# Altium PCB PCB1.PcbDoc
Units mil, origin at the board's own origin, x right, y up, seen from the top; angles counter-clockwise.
Board outline 3898.32 x 3898.32 mil, 2 copper layers (Top Layer, Bottom Layer); 54 components, 45 nets, 223 pads, 46 vias.
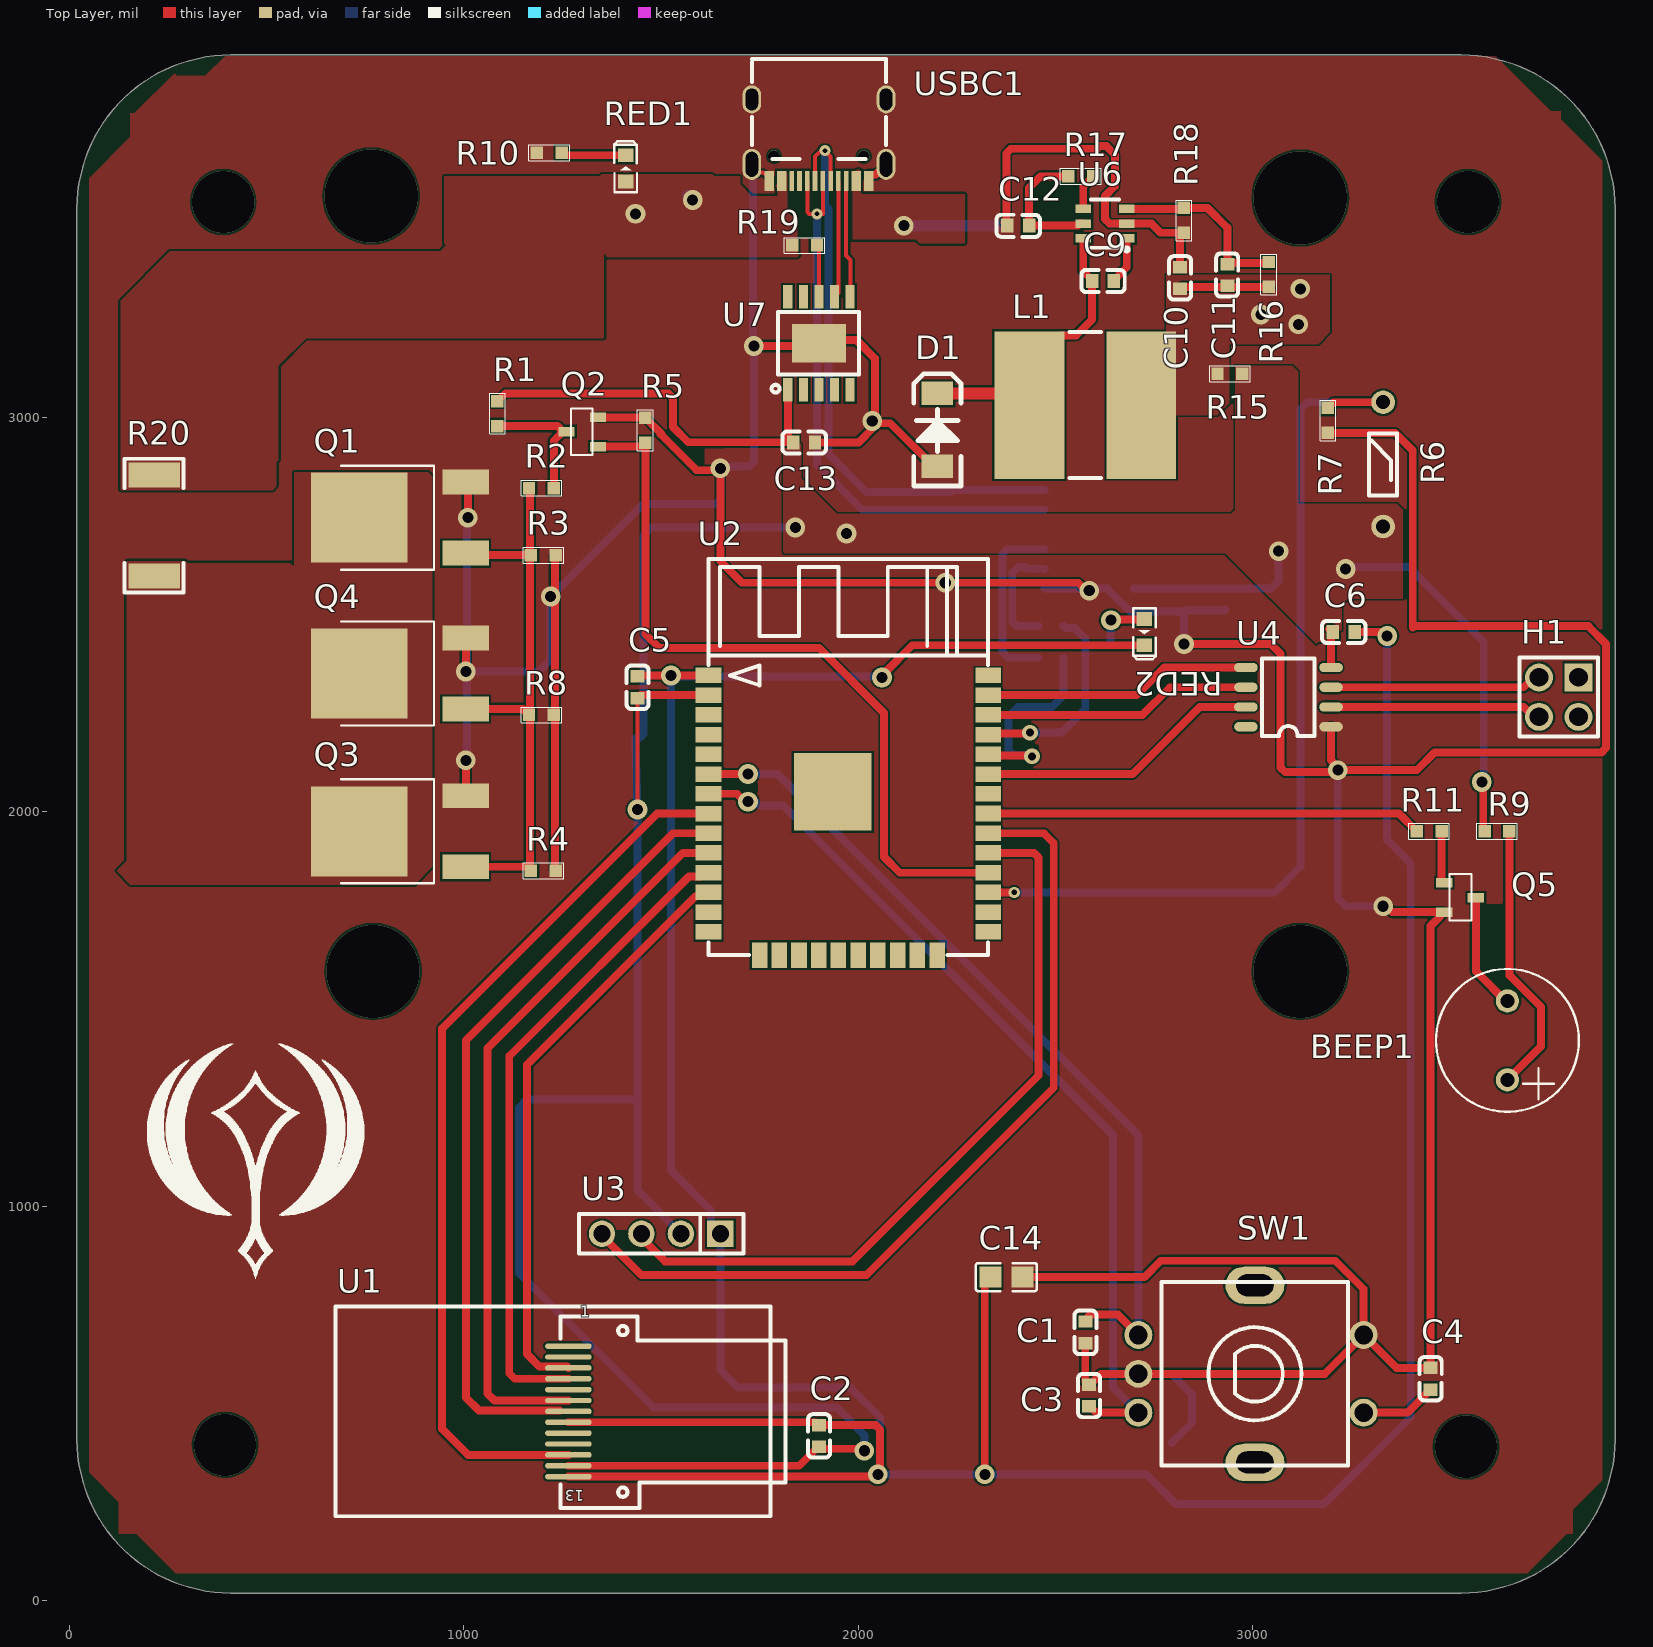
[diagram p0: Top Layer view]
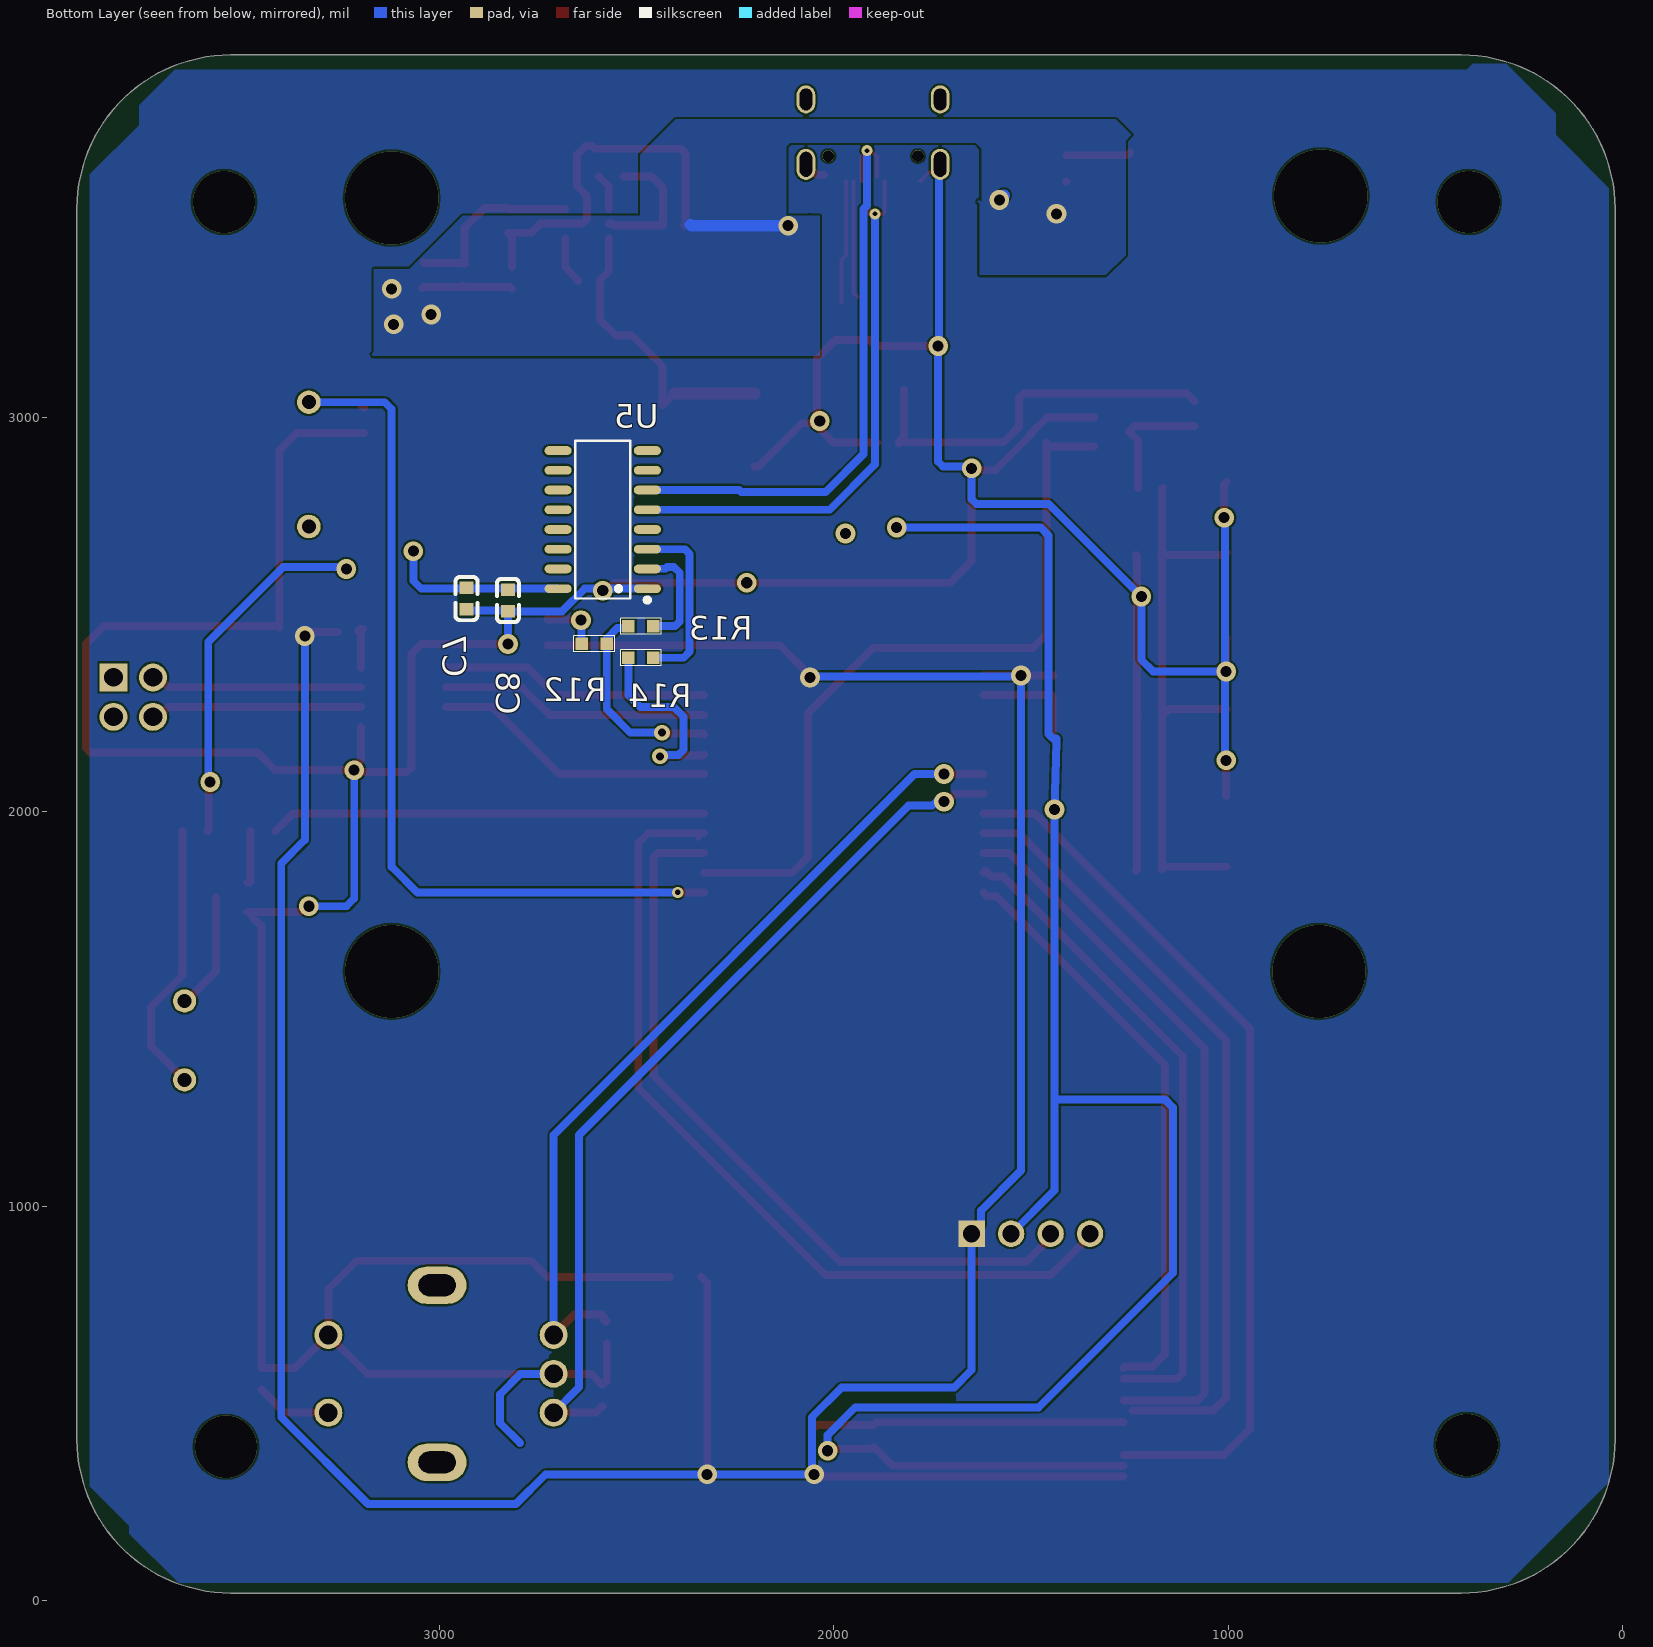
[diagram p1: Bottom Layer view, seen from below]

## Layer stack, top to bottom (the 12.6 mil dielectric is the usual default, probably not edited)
Top Solder: solder mask 0.4, Solder Resist, Dk 3.5
Top Layer: signal copper 1.4
Dielectric 1: dielectric 12.6, FR-4, Dk 4.8
Bottom Layer: signal copper 1.4
Bottom Solder: solder mask 0.4, Solder Resist, Dk 3.5

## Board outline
19.35,409.18 19.35,3527.83 cw(c409.18,3527.83) 409.18,3917.66 3527.83,3917.66 cw(c3527.83,3527.83) 3917.66,3527.83 3917.66,409.18 cw(c3527.83,409.18) 3527.83,19.35 409.18,19.35 cw(c409.18,409.18)

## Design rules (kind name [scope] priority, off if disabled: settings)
Clearance [All] p1: gap=5 ignorepadtopadclearanceinfootprint=TRUE
PolygonConnect [All] p1: connectstyle=Direct reliefconductorwidth=10 reliefentries=4 polygonreliefangle="90 Angle" airgapwidth=10
RoutingVias [All] p1: holewidth=28 width=50 viastyle="Through Hole" minholewidth=28 minwidth=50 maxholewidth=28 maxwidth=50
SolderMaskExpansion [All] p1: expansion=4
Width [All] p1: maxlimit=100 minlimit=10 preferedwidth=20
30 further rules are at their usual default settings.

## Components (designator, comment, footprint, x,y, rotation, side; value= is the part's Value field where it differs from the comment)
BEEP1 "BEEP-9.5X5.5" BEEP-9.5X5.5 3645,1420 r90 top
C1 "100nf" C0603 2575,680 r90 top
C2 "C0603" C0603 1900,417.56 r90 top
C3 "100nf" C0603 2585,520 r270 top
C4 "100nf" C0603 3450,562.56 r90 top
C5 "100NF" C0603 1440,2315 r90 top
C6 "C0603" C0603 3230,2455 r180 top
C7 "10UF" C0603 2930,2540 r270 bottom
C8 "0.1UF" C0603 2825,2535 r270 bottom
C9 "1UF" C0603 2620,3345 r0 top
C10 "100UF" C0603 2815,3352.56 r90 top
C11 "440P~660P" C0603 2935,3360 r270 top
C12 "10UF" C0603 2405,3485 r0 top
C13 "1uF" C0603 1862.44,2935 r180 top
C14 "C0805" C0805 2375,820 r180 top
D1 "SMAJ5.0CA" DO-214 2200,2875 r90 top
H1 "A2541WV-2X2P" HDR-TH_4P-P2.54-V-R2-C2-S2.54_A2541WV-2X2P 3775,2290 r180 top
L1 "6.8uH" IND-SMD_L10.0-W9.0 2575,3030 r0 top
Q1 "NCE3050K" TO-252-2_L6.6-W6.1-P4.57-LS10.1-TL-CW 869.81,2745 r180 top
Q2 "S8050" SOT-23 1340,2925 r90 top
Q3 "NCE3050K" TO-252-2_L6.6-W6.1-P4.57-LS10.1-TL-CW 869.81,1950 r180 top
Q4 "NCE3050K/NC" TO-252-2_L6.6-W6.1-P4.57-LS10.1-TL-CW 869.81,2350 r180 top
Q5 "S8050" SOT-23 3485,1819.8 r270 top
R1 "R0603" R_0603 1085,2977.01 r90 top value=3K
R2 "R0603" R_0603 1227.99,2820 r180 top value=100R
R3 "R0603" R_0603 1232.99,2650 r180 top value=100K
R4 "R0603" R_0603 1232.99,1850 r180 top value=100K
R5 "R0603" R_0603 1460,2997.99 r270 top value=10K
R6 "100kΩ/nc" RES-TH_BD1.8-L4.0-P8.00-D0.5 3330,2880 r90 top
R7 "R0603" R_0603 3190,3022.99 r270 top value=100K/nc
R8 "R0603" R_0603 1227.99,2245 r180 top value=10K/NC
R9 "R0603" R_0603 3650,1950 r180 top value=100R
R10 "R0603" R_0603 1247.99,3670 r180 top value=500R
R11 "R0603" R_0603 3415,1950 r0 top value=10K
R12 "R0603" R_0603 2575,2425 r0 bottom value=500R
R13 "R0603" R_0603 2520,2470 r180 bottom value=10R
R14 "R0603" R_0603 2520,2390 r180 bottom value=10R
R15 "R0603" R_0603 2910,3110 r0 top value=1K
R16 "R0603" R_0603 3040,3392.99 r270 top value=3.3K
R17 "R0603" R_0603 2595,3610 r180 top value=1M
R18 "R0603" R_0603 2825,3467.01 r90 top value=1K
R19 "R0603" R_0603 1895,3435 r180 top value=1K
R20 "加热板" R2512 215,2725 r90 top value=0.01Ω
RED1 "LED-0603_R" LED0603_RED 1410,3630 r90 top
RED2 "LED-0603_R" LED0603_RED 2725,2455 r270 top
SW1 "EC11" SW-TH_5P-L11.8-W12.0-P2.50-LS14.5 2995,575 r270 top
U1 "0.96 TFT" "0.96 LCD" 1265,479.76 r180 top
U2 "ESP32-WROOM-32" WIFIM-SMD_ESP-32S 1974.37,1990.55 r270 top
U3 "OLED" HDR-TH_4P-P2.54-V-M 1500,930 r180 top
U4 "MAX6675" SOIC-8_L5.0-W4.0-P1.27-LS6.0-BL 3090,2290 r90 top
U5 "CH340C" SOP-16_L10.0-W3.9-P1.27-LS6.0-BL 2585,2740 r90 bottom
U6 "ME3116" SOT-23-6_L2.9-W1.6-P0.95-LS2.8-BR 2625,3490 r0 top
U7 "CH224K" ESSOP10-EP 1900,3186.89 r90 top
USBC1 "TYPE-C-31-M-12" USB-C_SMD-TYPE-C-31-M-12 1899.92,3701.68 r180 top

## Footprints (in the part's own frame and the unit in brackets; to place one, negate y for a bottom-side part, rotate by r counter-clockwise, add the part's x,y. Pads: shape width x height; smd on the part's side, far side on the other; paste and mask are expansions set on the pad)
"0.96 LCD" [mm]
  oval 3x0.35 smd: 1(0,-4.2) 2(0,-3.5) 3(0,-2.8) 4(0,-2.1) 5(0,-1.4) 6(0,-0.7) 7(0,0) 8(0,0.7) 9(0,1.4) 10(0,2.1) 11(0,2.8) 12(0,3.5) 13(0,4.2)
  silkscreen extent -13.97,-6.75 15,6.75
BEEP-9.5X5.5 [mm]
  round 1.5 hole 0.9: 1(-2.54,0) 2(2.54,0)
  silkscreen extent -4.6,-4.6 4.6,4.6
C0603 [mm]
  rect 0.8x0.9 smd: 1(0.7,0) 2(-0.7,0)
  silkscreen extent -1.4,-0.72 1.4,0.7
C0805 [mm]
  rect 1.41x1.35 smd: 1(-1.03,0) 2(1.03,0)
  silkscreen extent -1.96,-0.9 1.96,0.9
DO-214 [mil]
  rect 60x80 smd: 1(0,0) 2(185,0)
  silkscreen extent -50,-60 235,60
ESSOP10-EP [mm]
  rect 2.5x3.5 smd: 0(0,0)
  rect 1.5x0.6 smd: 1(-3,2) 2(-3,1) 3(-3,0) 4(-3,-1) 5(-3,-2) 6(3,-2) 7(3,-1) 8(3,0) 9(3,1) 10(3,2)
  silkscreen extent -3.17,-2.57 2,3.05
HDR-TH_4P-P2.54-V-M [mm]
  rect 1.7x1.7 hole 1.1: 1(-3.81,0)
  round 1.7 hole 1.1: 2(-1.27,0) 3(1.27,0) 4(3.81,0)
  silkscreen extent -5.29,-1.27 5.29,1.27
HDR-TH_4P-P2.54-V-R2-C2-S2.54_A2541WV-2X2P [mm]
  rect 1.8x1.8 hole 1.2: 1(-1.27,-1.27)
  round 1.8 hole 1.2: 2(-1.27,1.27) 3(1.27,-1.27) 4(1.27,1.27)
  silkscreen extent -2.54,-2.54 2.54,2.54
IND-SMD_L10.0-W9.0 [mm]
  rect 4.5x9.5 smd: 1(-3.6,0) 2(3.6,0)
  silkscreen extent -1.02,-4.7 1.02,4.7
LED0603_RED [mm]
  rect 0.9x1 smd: 1(-0.85,0) 2(0.85,0)
  silkscreen extent -1.54,-0.73 1.75,0.73
R2512 [mm]
  rect 1.6x3.3 smd: 1(-3.25,0) 2(3.25,0)
  silkscreen extent -4.3,-1.9 4.3,1.9
R_0603 [mm]
  rect 0.8x0.8 smd: 1(0,0) 2(1.6,0)
  silkscreen extent -0.51,-0.51 2.11,0.51
RES-TH_BD1.8-L4.0-P8.00-D0.5 [mil]
  round 60 hole 35.43: 1(-157.48,0) 2(157.48,0)
  silkscreen extent -79,-35 79,35
SOIC-8_L5.0-W4.0-P1.27-LS6.0-BL [mm]
  oval 0.6x1.52 smd: 1(-1.905,-2.74) 2(-0.635,-2.74) 3(0.635,-2.74) 4(1.905,-2.74) 5(1.905,2.74) 6(0.635,2.74) 7(-0.635,2.74) 8(-1.905,2.74)
  silkscreen extent -2.49,-1.67 2.5,1.7
SOP-16_L10.0-W3.9-P1.27-LS6.0-BL [mm]
  oval 0.56x1.745 smd: 1(-4.445,-2.873) 2(-3.175,-2.873) 3(-1.905,-2.873) 4(-0.635,-2.873) 5(0.635,-2.873) 6(1.905,-2.873) 7(3.175,-2.873) 8(4.445,-2.873) 9(4.445,2.873) 10(3.175,2.873) 11(1.905,2.873) 12(0.635,2.873) 13(-0.635,2.873) 14(-1.905,2.873) 15(-3.175,2.873) 16(-4.445,2.873)
  silkscreen extent -5.33,-3.02 5.08,1.77
SOT-23 [mm]
  rect 0.6x1.05 smd: 1(0,0) 2(1.9,0) 3(0.965,2.032)
  silkscreen extent -0.55,0.35 2.45,1.75
SOT-23-6_L2.9-W1.6-P0.95-LS2.8-BR [mm]
  rect 1x0.55 smd: 1(1.4,-0.95) 2(1.4,0) 3(1.4,0.95) 4(-1.4,0.95) 5(-1.4,0) 6(-1.4,-0.95)
  silkscreen extent -0.9,-1.78 1.52,1.55
SW-TH_5P-L11.8-W12.0-P2.50-LS14.5 [mm]
  round 1.8 hole 1.2: 1(-2.5,-7.25) 2(0,-7.25) 3(2.5,-7.25) 4(-2.5,7.25) 5(2.5,7.25)
  oval 2.4x3.8 hole 1.4 slot 2.4 at 90 deg: 7(-5.7,0.25) 8(5.7,0.25)
  silkscreen extent -5.9,-5.75 5.9,6.25
TO-252-2_L6.6-W6.1-P4.57-LS10.1-TL-CW [mm]
  rect 3x1.6 smd: 1(-3.424,2.285) 3(-3.424,-2.285)
  rect 6.2x5.8 smd: 2(3.424,0)
  silkscreen extent -1.38,-3.35 4.58,3.35
USB-C_SMD-TYPE-C-31-M-12 [mm]
  oval 1.2x1.8 hole 0.8 slot 1.4 at 90 deg: 0(-4.32,-2.624) 0(4.32,-2.624)
  oval 1.2x2 hole 0.8 slot 1.6 at 90 deg: 0(-4.32,1.556) 0(4.32,1.556)
  rect 0.3x1.3 smd: A1(-3.35,2.623) A4(-2.55,2.623) A5(-1.25,2.623) A6(-0.25,2.623) A7(0.25,2.623) A8(1.25,2.624) A9(2.55,2.623) A12(3.35,2.623) B1(3.05,2.623) B4(2.25,2.623) B5(1.75,2.623) B6(0.75,2.623) B7(-0.75,2.623) B8(-1.75,2.624) B9(-2.25,2.623) B12(-3.05,2.623)
  round 0.75 hole 0.75 unplated: ""(-2.89,1.026) ""(2.89,1.026)
  silkscreen extent -4.32,-5.23 4.32,1.22
WIFIM-SMD_ESP-32S [mm]
  rect 1x1.65 smd: 1(-9.005,-9) 2(-7.735,-9) 3(-6.465,-9) 4(-5.195,-9) 5(-3.925,-9) 6(-2.655,-9) 7(-1.385,-9) 8(-0.115,-9) 9(1.155,-9) 10(2.425,-9) 11(3.695,-9) 12(4.965,-9) 13(6.235,-9) 14(7.505,-9) 25(7.505,9) 26(6.235,9) 27(4.965,9) 28(3.695,9) 29(2.425,9) 30(1.155,9) 31(-0.115,9) 32(-1.385,9) 33(-2.655,9) 34(-3.925,9) 35(-5.195,9) 36(-6.465,9) 37(-7.735,9) 38(-9.005,9)
  rect 1.65x1 smd: 15(9.005,-5.715) 16(9.005,-4.445) 17(9.005,-3.175) 18(9.005,-1.905) 19(9.005,-0.635) 20(9.005,0.635) 21(9.005,1.905) 22(9.005,3.175) 23(9.005,4.445) 24(9.005,5.715)
  rect 5x5 smd: 39(-1.51,-1)
  silkscreen extent -16.5,-9 9,9

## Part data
C1 C3 C4 C5 C7 C8 C9 C10 C11 C12 C13: library part C0603, BOM_Manufacturer="Samsung Electro-Mechanics", BOM_Manufacturer Part=10uF
C2 C6: BOM_Manufacturer="Samsung Electro-Mechanics", BOM_Manufacturer Part=10uF
C14: "Capacitor"
D1: "500V  400W 稳压管"
H1: library part 2X2P, BOM_JLCPCB Part Class="Extended Part", BOM_Manufacturer="Changjiang Connectors", BOM_Manufacturer Part=A2541WV-2x2P
L1: BOM_Manufacturer=LCSC, BOM_Manufacturer Part=SM1054-6R8MT
Q1 Q3: BOM_JLCPCB Part Class="Extended Part", BOM_Manufacturer=Ncepower
Q2 Q5: "NPN", Manufacturer #2=8050
Q4: library part NCE3050K, BOM_JLCPCB Part Class="Extended Part", BOM_Manufacturer=Ncepower
R6: library part "NTC 100kΩ", BOM_JLCPCB Part Class="Extended Part", BOM_Manufacturer=Shiheng, BOM_Manufacturer Part=MF58-104J3950F
R20: library part R2501, "R2501", BOM_JLCPCB SMD=Yes, BOM_Manufacturer=SUP, BOM_Manufacturer Part=MRF6432(2512)LR010JTS
RED1 RED2: BOM_Manufacturer=EVERLIGHT(台湾, BOM_Manufacturer Part=19-217/R6C-AL1M2VY/3T
SW1: BOM_JLCPCB Part Class="Extended Part", BOM_Manufacturer=BOURNS, BOM_Manufacturer Part=PEC11L-4115F-S0020
U2: BOM_JLCPCB Part Class="Extended Part", BOM_Manufacturer="Espressif Systems"
U3: library part "OLED module", BOM_Manufacturer=kinghelm(金航, BOM_Manufacturer Part=KH-2.54PH180-1X4P-L11.5
U4: BOM_LCSC Assembly=Yes, BOM_Manufacturer=MAXIM, BOM_Manufacturer Part=MAX6675ISA+T, Package Display=No
U5: BOM_JLCPCB Part Class="Extended Part", BOM_Manufacturer=WCH
U6: BOM_JLCPCB Part Class="Extended Part", BOM_Manufacturer=MICRONE
U7: BOM_Manufacturer=ÄÏ¾©Ç
USBC1: BOM_Manufacturer="Rectangular Connectors - Contacts"

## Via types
v1: diameter 50, hole 28, Top Layer to Bottom Layer, 33 vias
v2: diameter 236.22, hole 236.22, Top Layer to Bottom Layer, 4 vias
v3: diameter 157.48, hole 157.48, Top Layer to Bottom Layer, 4 vias
v4: diameter 28, hole 12, Top Layer to Bottom Layer, 2 vias
v5: diameter 40, hole 20, Top Layer to Bottom Layer, 2 vias
v6: diameter 28, hole 14, Top Layer to Bottom Layer, 1 vias

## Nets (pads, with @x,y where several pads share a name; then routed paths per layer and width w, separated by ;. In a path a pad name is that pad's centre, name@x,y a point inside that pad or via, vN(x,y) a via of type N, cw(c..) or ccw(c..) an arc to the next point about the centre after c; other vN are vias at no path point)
3.3V: C2.2 C5.2 C6.1 C7.2 C8.2 C13.1 R1.2 R6.1 R9.2 R15.2 U1.12 U2.2 U3.2 U4.4 U5.16 U7.1 | length 7774.1
  Top Layer w10: v1(1440,2005) C5.2@1440,2277.81 ; C5.2@1444.82,2282.63 C5.2@1440,2277.81 ; C5.2@1447.63,2295.07 C5.2 C5.2@1440,2277.81
  Top Layer w20: R1.2 1105,3060 1518.28,3060 1530,3048.28 1530,2975 1569.02,2935.98 C13.1@1834.89,2935.98 ; U1.12 1850,341.97 1898.03,390 1903.03,385 2010,385 v1(2015,380) ; C5.2@1447.63,2295.07 U2.2 ; U7.1 1821.26,2950.59 1834.89,2936.97 C13.1@1834.89,2935.98 ; C13.1@1834.89,2933.03 C13.1 C13.1@1834.89,2935.98 ; C6.1@3192.62,2463.19 3199.25,2463.19 3205,2457.44 3203.62,2457.44 3197.87,2451.7 U4.4 ; v1(3580,2075) 3583.5,2071.5 3583.5,1953.5 R9.2
  Bottom Layer w20: U3.2 1440,1040 1440,1275 ; v1(1840,2720) 1475,2720 1455,2700 1455,2196.72 1435.22,2176.95 ; v1(2015,380) 2015,420 1945,490 1480,490 1140,830 1140,1250 1160,1270 1435,1270 1440,1275 ; U5.16 3045,2565 3065,2585 v1(3065,2660) ; v1(3235,2615) 3240,2620 3395,2620 3585,2430 v1@3585,2065 ; 1435.22,2176.95 1435,2176.72 1435,2185 1435.22,2176.95 ; 1435.22,2176.95 v1(1440,2005) 1440,1275
  other v1: 1970,2705
GND: C1.2 C3.2 C4.1 C7.1 C8.1 C10.1 C12.2 C13.2 C14.1 D1.1 Q1.3 Q2.2 Q3.3 Q4.3 Q5.2 R3.1 R4.1 R5.1 R7.2 R8.1 R10.2 R18.1 SW1.2 SW1.4 U4.1 U5.1 U6.2 U7.0 USBC1.0 USBC1.A1 USBC1.A12 USBC1.B1 USBC1.B12 | length 14787.2
  Top Layer w10: USBC1.0@1742.43,3619.47 1758.78,3619.47 USBC1.B1
  Top Layer w20: Q3.3 1005,2040.35 v1(1005,2130) ; Q4.3 1005,2439.56 v1(1005,2355) ; Q1.3 1010,2829.56 v1(1010,2745) ; R4.1 1230.49,1852.5 1230.49,2242.5 R8.1 1230.49,2247.5 1230.49,2647.5 R3.1 ; Q2.2 1340.91,2998.9 1459.09,2998.9 R5.1 1500.67,2957.32 1497.68,2957.32 1590,2865 v1@1650,2865 ; v1(1650,2870) v1@1650,2865 ; USBC1.0@1729.84,3640.43 1729.84,3632.06 USBC1.0@1742.43,3619.47 ; v1(1735,3180) 1893.11,3180 U7.0 1908.11,3195 1995,3195 2041.72,3148.28 v1@2041.72,2984.26 ; C13.2 2000,2935 2041.72,2976.72 v1@2041.72,2984.26 ; USBC1.B12@2024.1,3614 2043.56,3614 2049.04,3619.47 2057.41,3619.47 2070,3632.06 USBC1.0@2070,3640.43 ; v1(2035,2990) 2040.74,2984.26 v1@2041.72,2984.26 ; USBC1.0@2067.59,3805 2070,3802.59 USBC1.0@2070,3805 ; D1.1 2190,2875 2080.74,2984.26 v1@2041.72,2984.26 ; C12.2@2369.73,3492.72 2371.7,3492.72 C12.2@2375,3489.41 ; C12.2 2375,3487.44 C12.2@2375,3489.41 ; C14.1 2724.92,820 2766.57,861.65 3208.35,861.65 3280.43,789.57 SW1.4 ; C3.2@2575,555.59 C1.2 ; C3.2 2586.97,547.56 2614.41,575 SW1.2 3182.01,575 SW1.4 ; v1(2585,2560) 2576.88,2560 2556.88,2580 v1(2220,2580) 1705,2580 1650,2635 v1@1650,2865 ; C10.1 2815,3457.01 R18.1 2765.61,3467.01 2742.62,3490 U6.2 2636.72,3490 2625,3501.72 2625,3560 2650,3585 2650,3665 2628.28,3686.72 2611.72,3686.72 2605,3680 2386.72,3680 2375,3668.28 C12.2@2375,3489.41 ; v1@2823.27,2423.27 v1(2825,2425) 3045,2425 3070,2400 3070,2111.72 3081.72,2100 3210,2100 v1(3215,2105) ; R7.2 3360,2960 3405,2915 3405,2466.72 3408.28,2470 3850,2470 3895,2425 3895,2161.72 3883.28,2150 3460,2150 3415,2105 v1(3215,2105) ; U4.1 3197.87,2130.24 3215,2113.12 v1(3215,2105) ; v1(3330,1760) 3338.12,1760 3353.12,1745 Q5.2@3476.14,1745 ; Q5.2 Q5.2@3476.14,1745 ; SW1.4 3363.74,590.11 C4.1 3450,1710 3474.33,1734.33 3474.33,1743.19 Q5.2@3476.14,1745
  Bottom Layer w20: v1(1005,2130) 1007.5,2132.5 v1@1007.5,2355 ; v1(1005,2355) v1@1007.5,2355 ; v1(1010,2745) 1007.5,2742.5 v1@1007.5,2355 ; USBC1.0@1729.84,3640.43 1732.42,3637.86 1732.42,3182.58 v1(1735,3180) 1735,2886.72 1723.28,2875 1655,2875 v1(1650,2870) 1650,2791.72 1638.28,2780 1455,2780 v1(1220,2545) 1220,2385 1190,2355 v1@1007.5,2355 ; U5.1 2630.83,2565 2688.38,2507.44 C8.1 ; SW1.2 2793.28,575 2845,523.28 2845,450 2795,400 ; v1(2825,2425) C8.1 ; C7.1 2927.5,2509.94 2827.5,2509.94 C8.1 ; v1(3215,2105) 3215,1780 3235,1760 v1(3330,1760)
NetBEEP1_1: BEEP1.1 R9.1 | length 698.3
  Top Layer w20: BEEP1.1 3730,1405 3730,1505 3650,1585 R9.1
NetBEEP1_2: BEEP1.2 Q5.3 | length 299.9
  Top Layer w20: Q5.3 3565,1595 BEEP1.2@3645,1515
NetC1_1: C1.1 SW1.1 U2.6 | length 2143.1
  Top Layer w20: U2.6 1620.08,2095.04 v1(1720,2095) v1(1720,2095) ; C1.1 2576.97,707.56 2582.72,713.3 2582.72,721 2586.72,725 2657.99,725 SW1.1
  Bottom Layer w20: v1(1720,2095) 1795,2095 2709.57,1180.43 SW1.1
NetC3_1: C3.1 SW1.3 U2.7 | length 2251.6
  Top Layer w20: U2.7 1691.81,2045.07 1711.88,2025 v1(1720,2025) ; C3.1 2586.97,492.44 2602.84,476.57 2696.57,476.57 2700,480 2703.43,476.57 SW1.3
  Bottom Layer w20: v1(1720,2025) 1725,2030 1735,2030 1750,2015 1810,2015 2645,1180 2645,541.14 SW1.3
NetC4_2: C4.2 SW1.5 | length 193.8
  Top Layer w20: SW1.5 3391.57,476.57 C4.2
NetC9_1: C9.1 U6.1 | length 121.1
  Top Layer w20: C9.1 2647.56,3346.97 2680.12,3379.53 U6.1
NetC9_2: C9.2 D1.2 L1.1 U6.6 | length 767.1
  Top Layer w20: L1.1@2403.27,3060 L1.1 2433.27,3128.43 2511.85,3207.01 2552.01,3207.01 2592.44,3247.44 C9.2 2592.44,3346.97 2569.88,3369.53 U6.6
  Top Layer w30: D1.2 L1.1@2403.27,3060
NetC11_2: C11.2 R16.1 R18.2 U6.3 | length 476.4
  Top Layer w20: U6.3 2822.4,3527.4 R18.2 2885,3530 2935,3480 C11.2 2937.72,3390.27 3037.28,3390.27 R16.1
NetC12_1: C12.1 R17.2 U6.5 | length 346.8
  Top Layer w20: R17.2 2461.72,3610 2432.56,3580.84 C12.1 2556.02,3485 2561.02,3490 U6.5
NetH1_3: H1.3 U4.3 | length 537.5
  Top Layer w20: U4.3 3686.24,2315 3711.24,2340 H1.3
NetH1_4: H1.4 U4.2 | length 537.5
  Top Layer w20: U4.2 3686.24,2265 3711.24,2240 H1.4
NetQ1_1: Q1.1 Q3.1 Q4.1 R2.2 R3.2 R4.2 R8.2 | length 1460.4
  Top Layer w20: Q3.1 R4.2@1159.96,1860.04 ; Q4.1 1149.96,2260.04 R8.2 ; Q1.1 1009.64,2650 R3.2@1167.5,2650 ; R2.2 1167.5,2817.5 R3.2@1167.5,2650 ; R4.2@1167.5,1852.5 1167.5,2242.5 R8.2 ; R3.2 R3.2@1168.75,2648.75 ; R8.2 1167.5,2247.5 1167.5,2647.5 R3.2@1168.75,2648.75 ; R3.2@1167.5,2650 R3.2@1168.75,2648.75
NetQ1_2: Q1.2 Q3.2 Q4.2 R20.1
NetQ2_1: Q2.1 R5.2 U2.28 | length 1942.2
  Top Layer w20: Q2.1 1450,2925 R5.2 1460,2450 1495,2415 1900,2415 2065,2250 2065,1885 2104.92,1845.08 U2.28
NetQ2_3: Q2.3 R1.1 R2.1 | length 324.5
  Top Layer w20: R1.1 1237.13,2977.01 1251.14,2963 1227.99,2939.85 R2.1
NetQ5_1: Q5.1 R11.2 | length 136.1
  Top Layer w20: R11.2 3477.99,1821.61 3479.8,1819.8 Q5.1
NetR6_2: R6.2 R7.1 U2.27 | length 2341.5
  Top Layer w20: U2.27 2328.73,1795.04 v6(2395,1795) v6(2395,1795) ; R7.1 3204.49,3037.48 R6.2
  Bottom Layer w20: v6(2395,1795) 3055,1795 3120,1860 3120,3020 3137.48,3037.48 R6.2
NetR10_1: R10.1 RED1.2 | length 164.7
  Top Layer w20: R10.1 1254.53,3663.46 RED1.2
NetR11_1: R11.1 U2.31 | length 1105
  Top Layer w20: U2.31 3369.92,1995.08 R11.1
NetR12_1: R12.1 R13.1 U2.35 | length 519.6
  Top Layer w20: U2.35 2331.15,2197.54 2432.54,2197.54 v5(2435,2200)
  Bottom Layer w20: v5(2435,2200) 2515,2200 2575,2260 R12.1 2575,2438.28 2548.28,2465 2525,2465 R13.1
NetR12_2: R12.2 RED2.1 | length 147.3
  Top Layer w20: v1(2640,2485) 2641.73,2486.73 2723.27,2486.73 RED2.1
  Bottom Layer w20: R12.2 2639,2426 2639,2484 v1(2640,2485)
NetR13_2: R13.2 U5.2 | length 285.3
  Bottom Layer w20: R13.2 2401.72,2470 2390,2481.72 2390,2605 2405,2620 2421.57,2620 2426.18,2615.39 2471.52,2615.39 U5.2
NetR14_1: R14.1 U2.34 | length 521.4
  Top Layer w20: U2.34 2331.23,2142.54 2437.46,2142.54 v5(2440,2140)
  Bottom Layer w20: v5(2440,2140) 2436.17,2143.83 2392.89,2143.83 2380,2156.72 2380,2240 2405,2265 2490,2265 2520,2295 R14.1
NetR14_2: R14.2 U5.3 | length 458.3
  Bottom Layer w20: R14.2 2380,2390 2365,2405 2365,2653.28 2376.72,2665 U5.3
NetR17_1: R17.1 U6.4 | length 93
  Top Layer w20: U6.4 2569.88,3584.88 R17.1
NetR19_1: R19.1 U7.8 | length 132.1
  Top Layer w10: R19.1 1900,3430 U7.8
NetU1_3: U1.3 U2.12 | length 1493.8
  Top Layer w20: U1.3 1261.89,593.11 1191.89,593.11 1160,625 1160,1358.41 1586.98,1785.39 1610.36,1785.39 U2.12
NetU1_4: U1.4 U2.11 | length 1661
  Top Layer w20: U1.4 1129.27,562.44 1115,576.72 1115,1380 1570.39,1835.39 1600.39,1835.39 1615,1850 1619.93,1845.07 U2.11
NetU1_5: U1.5
NetU1_6: U1.6 U2.10 | length 1852.6
  Top Layer w20: U1.6 1077.38,507.32 1060,524.71 1060,1400 1555.07,1895.07 U2.10
NetU1_7: U1.7 U2.9 | length 1988.7
  Top Layer w20: U1.7@1242.38,481.72 1038.28,481.72 1005,515 1005,1420 1530.07,1945.07 U2.9
NetU1_11: U1.11 U2.8 | length 2262.9
  Top Layer w20: U1.11 1010.47,369.53 945,435 945,1450 1490.07,1995.07 U2.8
NetU2_29: U2.29 U3.3 | length 1925.7
  Top Layer w20: U3.3@1440,930 1445,925 1510,860 1985,860 2456.79,1331.79 2456.79,1883.36 2445.08,1895.08 U2.29
NetU2_30: U2.30 U3.4 | length 2214.8
  Top Layer w10: U2.30 U2.30@2343.38,1930.39
  Top Layer w20: U3.4@1340,935 1347.5,927.5 1450,825 2020,825 2495,1300 2495,1920 2469.92,1945.08 U2.30
NetU2_33: U2.33 U4.7 | length 723.8
  Top Layer w20: U2.33 2695.08,2095.08 2865,2265 U4.7
NetU2_36: U2.36 U4.6 | length 682.4
  Top Layer w20: U2.36 2720.08,2245.08 2790,2315 U4.6
NetU2_37: U2.37 U4.5 | length 682.4
  Top Layer w20: U2.37 2705.08,2295.08 2775,2365 U4.5
NetU5_5: U5.5 USBC1.A6 USBC1.B6 | length 1444.9
  Top Layer w10: USBC1.B6 1870.39,3519.61 1875,3515 v4(1895,3515) 1910,3515 USBC1.A6@1910,3580
  Bottom Layer w20: v4(1895,3515) 1895,2880 2010,2765 U5.5
NetU5_6: U5.6 USBC1.A7 USBC1.B7 | length 1530.4
  Top Layer w10: USBC1.A7@1890,3610 1890,3660 1910,3680 v4(1915,3675) 1929.45,3660.55 USBC1.B7
  Bottom Layer w20: v4(1915,3675) 1915,3536.01 1924,3527.01 1924,2906 2020,2810 2234.01,2810 2239.01,2815 U5.6
NetU7_6: U7.6 USBC1.B8 | length 313
  Top Layer w10: USBC1.B8 1968.82,3409.25 1980,3398.07 U7.6@1980,3290
NetU7_7: U7.7 USBC1.A5 | length 297.5
  Top Layer w10: U7.7 1949.13,3314.76 USBC1.A5
PGND: C2.1 C5.1 C6.2 C14.2 RED2.2 U1.8 U1.13 U2.1 U3.1 | length 9591.5
  Top Layer w10: C5.1 C5.1@1442.51,2345.07
  Top Layer w20: U1.13 2043.28,314.41 v1(2049.14,320.27) 2055,326.13 2055,433.28 2043.28,445 1898.15,445 1890.94,452.2 U1.8 ; C5.1@1442.51,2345.07 U2.1 ; v1@2065,2350 2136.54,2421.54 RED2.2 ; v1(2320.27,320.27) 2320.27,805.82 C14.2 ; C6.2 3321.88,2455 3331.88,2445 v1(3340,2445)
  Bottom Layer w20: v1(2060,2340) 2057.5,2342.5 1527.5,2342.5 v1(1525,2345) 1525,1090 1626.54,988.46 1626.54,953.46 U3.1 1650,585 1695,540 1980,540 2055,465 2055,363.43 2054.88,363.31 2054.88,326.01 v1(2049.14,320.27) v1(2320.27,320.27) 2729.73,320.27 2805,245 3180,245 3400,465 3400,1868.44 3340,1928.44 v1(3340,2445)
VBUS1: C10.2 C11.1 L1.2 R15.1 R16.2 R19.2 R20.2 RED1.1 USBC1.A4 USBC1.A9 USBC1.B4 USBC1.B9 | length 518.9
  Top Layer w20: RED1.1 RED1.1@1411.53,3596.53 ; C10.2 2820,3330 C11.1@2945,3330 ; C11.1 2942.56,3332.44 C11.1@2945,3330 ; R16.2@3042.5,3327.5 R16.2 C11.1@2945,3330 ; v1@3115,3320 v1(3120,3325) v1@3117.5,3327.5
  Bottom Layer w30: v1@1568.28,3561.72 v1(1580,3550) ; v1(2115,3485) 2360,3485 2362.5,3487.5
  other v1: 3115,3235 3020,3260 1435,3515
pads on no net: H1.1 H1.2 SW1.7 SW1.8 U1.1 U1.2 U1.9 U1.10 U2.3 U2.4 U2.5 U2.13 U2.14 U2.15 U2.16 U2.17 U2.18 U2.19 U2.20 U2.21 U2.22 U2.23 U2.24 U2.25 U2.26 U2.32 U2.38 U2.39 U4.8 U5.4 U5.7 U5.8 U5.9 U5.10 U5.11 U5.12 U5.13 U5.14 U5.15 U7.2 U7.3 U7.4 U7.5 U7.9 U7.10 USBC1. USBC1.A8 USBC1.B5
copper on no net:
  other v2: 770,1595 3120,1595 3120,3555 765,3560
  other v3: 3540,390 395,395 390,3545 3545,3545

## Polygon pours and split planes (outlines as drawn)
GND on Top Layer "Top Layer-GND" (solid, pour order 21): 270,3865 345,3865 395,3915 3615,3915 3755,3775 3780,3775 3780,3755 3885,3650 3885,305 3810,230 3810,170 3795,170 3695,70 270,70 170,170 125,170 125,250 50,325 50,3605 155,3710 155,3770 165,3770 270,3875
VBUS1 on Top Layer "Top Layer-VBUS1" (solid, pour order 2): 1815,3625 1820,3620 1820,3520 1830,3510 1845,3510 1845,3415 1850,3410 1845,3405 1365,3405 1335,3435 1335,3600 1350,3615 1630,3615 1635,3610 1700,3610 1700,3590 1730,3560 1795,3560 1795,3580 1790,3585
3.3V on Top Layer "Top Layer-3.3V" (solid, pour order 14): 2955,3130 3100,3130 3115,3115 3115,2780 3365,2780 3380,2765 3380,2540 3240,2540 3225,2525 3225,2430 3165,2430 3160,2425 2930,2655 1805,2655 1810,2660 1810,2950 1850,2950 1855,2955 1855,2845 1945,2755 2945,2755 2955,2765
VBUS1 on Top Layer "Top Layer-VBUS1 1" (solid, pour order 16): 1355,3200 600,3200 530,3130 530,2890 525,2885 525,2825 515,2815 130,2815 130,3295 255,3420 940,3420 955,3435 950,3440 950,3610 1355,3610
NetQ1_2 on Top Layer "Top Layer-NetQ1_2" (solid, pour order 18): 560,2630 570,2620 570,2860 910,2860 920,2850 920,1860 875,1815 155,1815 120,1850 145,1875 145,2635 295,2635 300,2630
VBUS1 on Top Layer "Top Layer-VBUS1 2" (solid, pour order 8): 3195,3360 3195,3215 3165,3185 2940,3185 2940,3035 2910,3005 2780,3005 2780,3360
VBUS1 on Top Layer "Top Layer-VBUS1 3" (solid, pour order 4): 1980,3620 1985,3615 1985,3450 2145,3450 2155,3440 2270,3440 2270,3565 2010,3565 2005,3570 2005,3630
PGND on Bottom Layer "Bottom Layer-PGND" (solid, pour order 23): 285,3890 290,3895 380,3895 395,3880 3670,3880 3760,3790 3760,3740 3885,3615 3885,290 3785,190 3785,170 3660,45 290,45 35,300 35,3580 170,3715 170,3770 290,3890
VBUS1 on Bottom Layer "Bottom Layer-VBUS1" (solid, pour order 19): 1650,3560 1630,3540 1630,3360 1310,3360 1260,3410 1260,3700 1245,3715 1285,3755 2400,3755 2490,3665 2490,3505 2130,3505 2120,3495 2120,3685 2110,3695 1640,3695 1625,3680 1625,3545
VBUS1 on Bottom Layer "Bottom Layer-VBUS1 1" (solid, pour order 6): 2055,3515 2060,3510 2940,3510 3075,3375 3165,3375 3165,3165 3175,3155 2035,3155 2035,3510 2065,3510

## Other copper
Top Layer:
  pour cut-out: 1560,2925 1655,2925 1660,2920 1610,2920 1610,2880 1595,2880 1555,2920
  pour cut-out: 2554.58,3543.23 2550.36,3547.46 2550.36,3589.1 2550.36,3589.25 2473.5,3589.25 2468.05,3594.71 2447.85,3574.51 2447.85,3507.72 2453.3,3507.72 2453.3,3500.29 2545.19,3500.29 2550.73,3505.83 2594.56,3505.83 2594.56,3511.57 2545.19,3511.57 2545.19,3543.23
  pour cut-out: 1988.45,840.29 2013.67,840.29 2479.71,1306.34 2479.71,1913.67 2463.59,1929.78 2366.17,1929.78 2366.17,1913.91 2369.71,1910.37 2451.41,1910.37 2455.89,1905.89 2455.89,1904.25 2470.92,1889.21 2470.92,1325.94 2468.6,1325.94 1987.96,845.29
  pour cut-out: 1506.55,840.29 1506.55,844.8 1507.05,845.29 1460.3,892.04 1440.45,892.04 1412.53,919.96 1412.53,940.04 1387.47,940.04 1384.31,936.88 1384.31,912.32 1456.33,840.29 1506.55,840.29 1507.05,840.79 1507.05,845.29
  pour cut-out: 2369.71,2260.37 2366.17,2263.91 2366.17,2279.78 2367.34,2280.95 2715.95,2280.95 2781.34,2346.34 2781.34,2349.71 3006.25,2349.71 3006.8,2349.16 3010.51,2352.88 3012.36,2352.88 3012.36,2325.27 3005.49,2332.14 2947.14,2332.14 2944.13,2329.13 2782.5,2329.13 2713.74,2260.37 2369.71,2260.37 2369.71,2276.25 2366.17,2279.78
  pour cut-out: 2369.71,2157.83 2366.17,2161.37 2366.17,2174.76 2373.39,2181.98 2439.23,2181.98 2451.2,2170 2455,2170 2458.02,2166.98 2458.02,2158.02 2435.77,2158.02 2430.25,2163.55 2416.7,2150 2377.54,2150 2369.71,2157.83 2369.71,2171.23 2366.17,2174.76
  pour cut-out: 1825,3570 1860,3570 1860,3515 1870,3505 1880,3505 1890,3495 1905,3495 1915,3505 1915,3515 1920,3520 1920,3570 1940,3570 1940,3340 1925,3340 1925,3275 1920,3270 1915,3270 1915,3340 1910,3340 1915,3345 1915,3455 1850,3455 1850,3515 1840,3515 1835,3520 1830,3520 1825,3525
  pour cut-out: 1660,2060 1660,2080 1695,2080 1695,2075 1700,2070 1745,2070 1745,2050 1735,2050 1730,2055 1715,2055 1710,2050 1705,2050 1705,2055 1700,2060
  pour cut-out: 1580,2280 1465,2280 1465,2275.38 1468.18,2272.2 1460.98,2265 1450,2265 1450,2035 1455,2030 1455,2025 1470,2010 1470,2005 1475,2000 1480,2000 1495,2015 1580,2015
  pour cut-out: 3655,1560 3635,1580 3635,1770 3630,1765 3575,1765 3580,1760 3580,1600 3625,1555 3625,1550 3635,1550 3645,1560 3650,1560 3655,1555
  pour cut-out: 2035,355 2040,360 2040,350 2035,350 2030,345 2025,345 2025,330 1860,330 1860,335 1865,340 1877.68,340 1900.24,362.56 1972.56,362.56 1980,370 1990,360 2000,360 2010,350 2035,350 2040,355
  pour cut-out: 1180,580 1180,585 1145,620 1145,1365 1585,1805 1585,1820 1575,1820 1130,1375 1130,585 1135,580 1135,575 1175,575
  pour cut-out: 1200,525 1200,550 1115,550 1105,560 1105,565 1100,570 1100,1390 1560,1850 1580,1850 1580,1875 1585,1880 1580,1885 1565,1885 1075,1395 1070,1395 1075,1390 1075,530 1080,525
  pour cut-out: 1060,495 1045,495 1020,520 1020,1415 1535,1930 1580,1930 1580,1910 1550,1910 1045,1405 1045,535 1050,530 1050,515 1055,510 1055,505 1060,500
  pour cut-out: 1325,430 1330,425 1320,415 1320,405 1325,405 1325,385 1320,385 1320,375 1325,370 1330,370 1325,365 1325,355 1845,355 1845,363.21 1880,398.21 1880,410 1920,410 1920,405 1925,400 2015,400 2025,410 2030,405 2040,405 2040,425 2035,430 1925,430 1920,425 1876.44,425 1866.44,435 1330,435
  pour cut-out: 1200,405 1205,410 1205,415 1200,420 1200,435 1205,440 1205,465 1200,470 1030,470 990,510 990,1430 1520,1960 1570,1960 1585,1975 1585,1980 1495,1980 960,1445 960,440 1015,385 1205,385 1205,390 1200,395
Bottom Layer:
  pour cut-out: 1704.87,2067.34 1703.41,2068.8 1735.17,2068.8 1746.08,2079.71 1788.67,2079.71 2694.28,1174.1 2694.28,710.85 2691.29,710.85 2668.79,688.35 2668.79,658.49 2694.64,632.64 2709.57,632.64 2720.13,622.08 2720.13,614.39 2693.25,614.39 2670.18,591.32 2670.18,564.44 2680.73,553.89 2680.73,546.16 2688.46,546.16 2699.01,535.61 2708.18,535.61 2709.57,534.22 2709.57,517.35 2706.07,513.85 2693.92,513.85 2660.29,547.47 2660.29,1184.71 1815.87,2029.13 1780.87,2029.13 1775,2035 1761.04,2035 1756.33,2030.29 1735.42,2051.2 1704.87,2051.2
  pour cut-out: 2034.71,402.69 2036.92,404.9 2039.71,404.9 2039.71,458.67 1973.67,524.71 1695,524.71 1690,519.71 1690,505 1690.87,504.13 1950.85,504.13 2024.17,430.81 2025.81,430.81 2025.81,424.48 2030.29,420 2030.29,406.08 2033.68,402.69 2037.5,402.69 2039.71,404.9 2039.71,458.67
  pour cut-out: 2694.72,2522.74 2673.68,2543.78 2675.87,2545.97 2675.87,2548.66 2676.91,2549.71 2802.28,2549.71 2802.28,2541.81 2847.72,2541.81 2847.72,2549.71 2907.28,2549.71 2907.28,2546.81 2952.72,2546.81 2952.72,2533.19 2907.28,2533.19 2907.28,2525.24 2847.72,2525.24 2847.72,2528.19 2802.28,2528.19 2802.28,2522.74 2694.72,2522.74 2673.68,2543.78 2675.87,2545.97 2675.87,2548.66
  pour cut-out: 2501.49,2642.41 2494.19,2649.71 2383.05,2649.71 2380.29,2646.95 2380.29,2623.46 2383,2623.46 2384.91,2621.54 2398.67,2635.29 2405,2635.29 2406.16,2634.13 2429.07,2634.13 2432.51,2630.69 2502.66,2630.69 2506.79,2626.55 2506.79,2644.61 2501.49,2649.91
  pour cut-out: 1910.29,2886.33 1910.29,2891.01 1913.22,2891.01 1915.29,2893.08 2013.67,2794.71 2020,2794.71 2021.16,2795.87 2241.51,2795.87 2245.55,2799.91 2501.49,2799.91 2506.79,2794.61 2506.79,2776.55 2447.08,2776.55 2443.34,2780.29 2016.33,2780.29 1910.29,2886.33 1915.29,2891.33 1915.29,2893.08

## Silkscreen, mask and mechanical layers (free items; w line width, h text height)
Top Overlay:
  drawing of 2255 lines, arcs and shapes, not listed
Mechanical 1:
  circle w0.5: c393.7,393.7 r78.74
  circle w0.5: c3543.31,393.7 r78.74
  circle w0.5: c3543.31,3543.31 r78.74
  circle w0.5: c393.7,3543.31 r78.74
  circle w0.5: c766.68,1593.1 r118.06
  circle w0.5: c3124.47,1593.1 r118.11
  circle w0.5: c3124.47,3559.46 r119.66
  circle w0.5: c766.68,3559.46 r118.11
  circle w0.5: c393.7,393.7 r78.74
  circle w0.5: c3543.31,393.7 r78.74
  circle w0.5: c3543.31,3543.31 r78.74
  circle w0.5: c393.7,3543.31 r78.74
  lines w0.5: 409.18,3919.77 3527.83,3919.77 ; 648.57,1593.1 766.68,1593.1 766.68,1474.99 ; 648.57,3559.46 766.68,3559.46 766.68,3677.57 ; 3124.47,1474.99 3124.47,1593.1 3242.58,1593.1 ; 3124.47,3677.57 3124.47,3559.46 3242.58,3559.46 ; 19.35,409.18 ccw(c409.18,409.18) 409.18,19.35 ; 19.35,409.18 ccw(c409.18,409.18) 409.18,19.35 ; 19.35,409.18 19.35,3527.83 ; 19.35,409.18 19.35,3527.83 ; 19.35,3527.83 cw(c409.18,3527.83) 409.18,3917.66 ; 19.35,3527.83 cw(c409.18,3527.83) 409.18,3917.66 ; 409.18,19.35 3527.83,19.35 ; 409.18,19.35 3527.83,19.35 ; 409.18,3917.66 3527.83,3917.66 ; 3527.83,19.35 ccw(c3527.83,409.18) 3917.66,409.18 ; 3527.83,19.35 ccw(c3527.83,409.18) 3917.66,409.18 ; 3527.83,3917.66 cw(c3527.83,3527.83) 3917.66,3527.83 ; 3527.83,3917.66 cw(c3527.83,3527.83) 3917.66,3527.83 ; 3917.66,409.18 3917.66,3527.83 ; 3917.66,409.18 3917.66,3527.83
